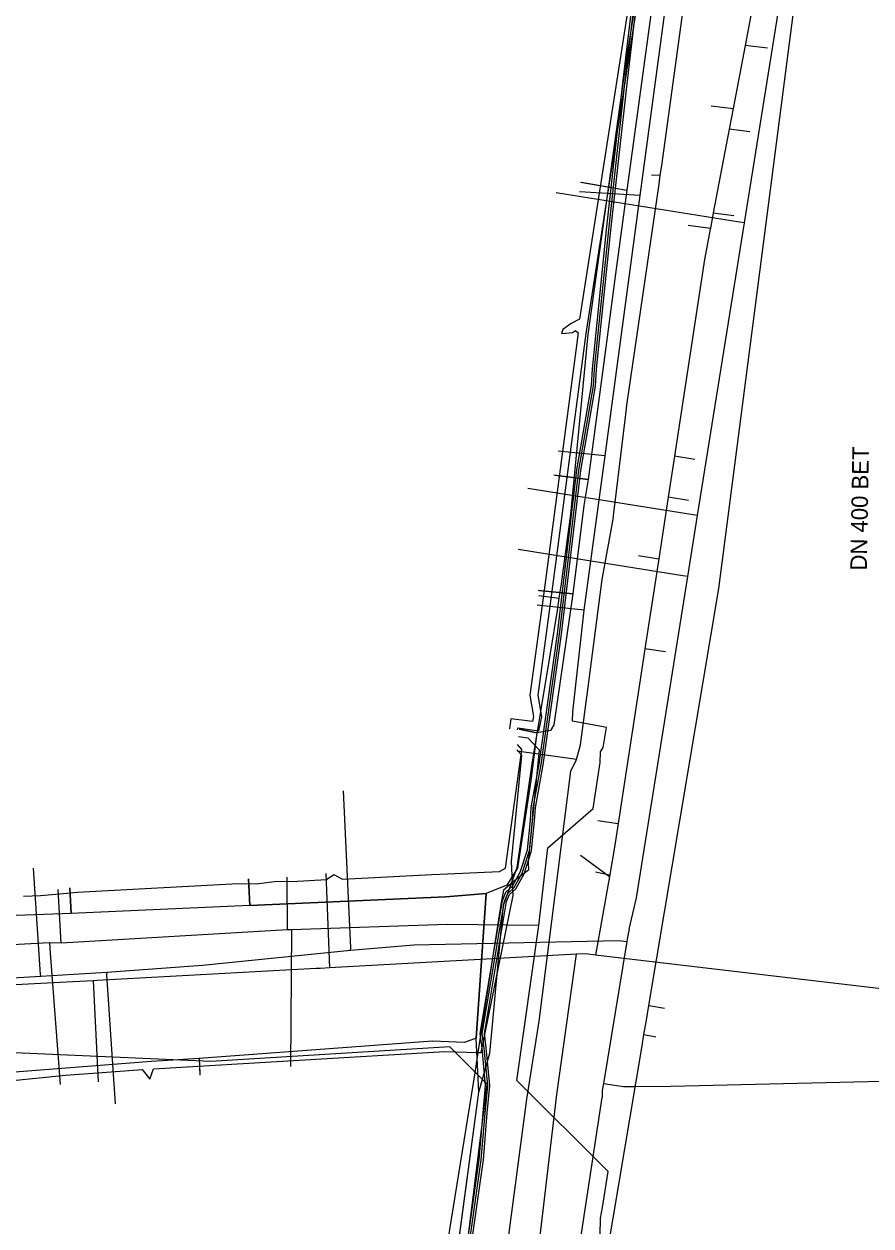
# Model space of a CAD drawing. Extents: x -596228 to -595156, y -1161235 to -1159373.
# Drawn here: x -595422.6 to -595381.6, y -1160891.1 to -1160832.9 of the extents above; entities that cross this region are included whole.
import ezdxf

# ---------------------------------------------------------------- set-up
doc = ezdxf.new("R2010")
doc.units = 0
for name, color, linetype in [('Vrstva 1', 7, 'Continuous'), ('Vrstva 12', 7, 'Continuous'), ('Vrstva 14', 7, 'Continuous'), ('Vrstva 16', 7, 'Continuous'), ('Vrstva 19', 7, 'Continuous'), ('Vrstva 4', 7, 'Continuous'), ('Vrstva 42', 7, 'Continuous'), ('Vrstva 44', 7, 'Continuous'), ('Vrstva 55', 7, 'Continuous'), ('Vrstva 58', 7, 'Continuous'), ('Vrstva 9', 7, 'Continuous')]:
    doc.layers.add(name, color=color, linetype=linetype)

msp = doc.modelspace()

# ---------------------------------------------------------------- linework, layer by layer
at = {"layer": 'Vrstva 1'}
for p, q in [((-595395.692, -1160873.187), (-595394.294, -1160874.206)), ((-595408.036, -1160874.065), (-595407.854, -1160878.639))]:
    msp.add_line(p, q, dxfattribs=at)
at = {"layer": 'Vrstva 12'}
for p, q in [((-595391.27, -1160824.92), (-595393.45, -1160840.98)), ((-595395.69, -1160840.59), (-595393.45, -1160840.98)), ((-595396.93, -1160854.78), (-595395.33, -1160854.98)), ((-595397.69, -1160860.37), (-595396.06, -1160860.53)), ((-595396.73, -1160860.73), (-595396.61, -1160860.04)), ((-595397.72, -1160860.6), (-595396.73, -1160860.73)), ((-595398.66, -1160867.08), (-595397.81, -1160867.26)), ((-595411.77, -1160874.32), (-595411.71, -1160875.61)), ((-595420.43, -1160874.78), (-595420.37, -1160876)), ((-595400.27, -1160875.03), (-595400.75, -1160882.05)), ((-595411.71, -1160875.61), (-595420.37, -1160876)), ((-595400.62, -1160884.65), (-595400.75, -1160882.05)), ((-595414.16, -1160883.02), (-595414.13, -1160883.84)), ((-595401.54, -1160891.52), (-595400.62, -1160884.65))]:
    msp.add_line(p, q, dxfattribs=at)
for points in [[(-595396.61, -1160860.04), (-595396.17, -1160856.67), (-595395.33, -1160847.96), (-595393.5, -1160834.87), (-595391.96, -1160825.25), (-595391.27, -1160820.29), (-595390.52, -1160814.98), (-595390.53, -1160811.25)], [(-595393.45, -1160840.98), (-595394, -1160845.02), (-595394.44, -1160848.34), (-595395.33, -1160854.98)], [(-595395.33, -1160854.98), (-595395.54, -1160856.24), (-595396.06, -1160860.53)], [(-595396.06, -1160860.53), (-595396.98, -1160866.87), (-595397.14, -1160867.14), (-595397.81, -1160867.26)], [(-595400.62, -1160884.65), (-595400.09, -1160882.77), (-595399.97, -1160881.57), (-595399.42, -1160875.6), (-595398.77, -1160873.77), (-595398.04, -1160868.75), (-595397.15, -1160863.4), (-595396.81, -1160861.33), (-595396.73, -1160860.73)], [(-595397.81, -1160867.26), (-595398.1, -1160869.57), (-595398.74, -1160873.81), (-595399.27, -1160874.63), (-595400.27, -1160875.03)], [(-595411.71, -1160875.61), (-595402.22, -1160875.2), (-595400.27, -1160875.03)], [(-595420.37, -1160876), (-595429.24, -1160876.32), (-595436.21, -1160876.71), (-595440.47, -1160876.95)], [(-595400.75, -1160882.05), (-595401.31, -1160882.25), (-595402.87, -1160882.19), (-595414.16, -1160883.02)], [(-595414.16, -1160883.02), (-595416.47, -1160883.18), (-595423.94, -1160883.76), (-595428.13, -1160883.87), (-595432.5, -1160883.79)]]:
    msp.add_lwpolyline(points, dxfattribs=at)
at = {"layer": 'Vrstva 14'}
for p, q in [((-595393.342, -1160876.76), (-595393.4, -1160877.07)), ((-595393.449, -1160877.36), (-595394.58, -1160884.23)), ((-595393.84, -1160877.31), (-595393.45, -1160877.36)), ((-595393.4, -1160877.07), (-595393.449, -1160877.36)), ((-595392.505, -1160881.174), (-595392.386, -1160880.463)), ((-595392.386, -1160880.463), (-595391.63, -1160880.59)), ((-595392.622, -1160881.872), (-595392.505, -1160881.174)), ((-595392.622, -1160881.872), (-595392.04, -1160881.97)), ((-595394.58, -1160884.23), (-595394.64, -1160884.58)), ((-595394.58, -1160884.23), (-595393.62, -1160884.38)), ((-595393.04, -1160884.38), (-595393.042, -1160884.331)), ((-595394.64, -1160884.58), (-595394.65, -1160884.91))]:
    msp.add_line(p, q, dxfattribs=at)
for points in [[(-595392.386, -1160880.463), (-595389, -1160860.26), (-595382.285, -1160808.426), (-595374.317, -1160746.92), (-595371.904, -1160743.843), (-595363.417, -1160733.399), (-595367.988, -1160714.713), (-595370.468, -1160704.744)], [(-595393.342, -1160876.76), (-595392.99, -1160875.24), (-595390.499, -1160859.689), (-595390.026, -1160856.737), (-595387.754, -1160842.558), (-595386.046, -1160831.895), (-595382.445, -1160809.421), (-595378.386, -1160784.054), (-595376.306, -1160771.081), (-595374.576, -1160760.301), (-595372.949, -1160750.146)], [(-595387.754, -1160842.558), (-595387.99, -1160842.52), (-595396.866, -1160841.098)], [(-595390.026, -1160856.737), (-595390.241, -1160856.702), (-595398.246, -1160855.42)], [(-595390.499, -1160859.689), (-595390.742, -1160859.65), (-595398.715, -1160858.373)], [(-595406.84, -1160877.78), (-595406.825, -1160877.67), (-595407.171, -1160870.06)], [(-595421.83, -1160879.04), (-595421.846, -1160878.961), (-595422.188, -1160873.816)], [(-595480.35, -1160881.13), (-595476.74, -1160881.06), (-595458.05, -1160880.32), (-595455.86, -1160880.24), (-595452.25, -1160880.1), (-595447.07, -1160879.89), (-595446.23, -1160879.85), (-595441.06, -1160879.64), (-595438.31, -1160879.54), (-595435.699, -1160879.51), (-595435.21, -1160879.51), (-595434.81, -1160879.5), (-595432.905, -1160879.416), (-595427.729, -1160879.309), (-595426.15, -1160879.29), (-595425.714, -1160879.268), (-595421.83, -1160879.04), (-595418.64, -1160878.84), (-595414.01, -1160878.51), (-595406.84, -1160877.78), (-595403.77, -1160877.53), (-595393.84, -1160877.31)], [(-595418.64, -1160878.84), (-595418.65, -1160878.98), (-595418.239, -1160885.223)], [(-595411.29, -1161007.18), (-595405.35, -1160965.21), (-595403.324, -1160946.542), (-595403.072, -1160944.755), (-595398.92, -1160914.75), (-595397.23, -1160913.67), (-595395.51, -1160899.1), (-595392.712, -1160882.407), (-595392.622, -1160881.872)], [(-595393.62, -1160884.38), (-595393.04, -1160884.38), (-595391.32, -1160884.36), (-595368.12, -1160883.82)], [(-595403.586, -1160941.38), (-595401.229, -1160926.663), (-595399.42, -1160915.372), (-595397.797, -1160905.243), (-595396.846, -1160899.305), (-595396.485, -1160897.021), (-595394.65, -1160884.91)]]:
    msp.add_lwpolyline(points, dxfattribs=at)
at = {"layer": 'Vrstva 16'}
for p, q in [((-595392.25, -1160840.24), (-595391.83, -1160840.25)), ((-595395.89, -1160868.54), (-595398.76, -1160868.14))]:
    msp.add_line(p, q, dxfattribs=at)
msp.add_lwpolyline([(-595399.71, -1160895.73), (-595398.29, -1160884.99), (-595397.7, -1160881.22), (-595396.17, -1160869.12), (-595395.89, -1160868.54), (-595395.69, -1160867.84), (-595395.33, -1160865.05), (-595394.65, -1160859.83), (-595394.12, -1160856.91), (-595394.08, -1160856.58), (-595394.019, -1160856.08), (-595393.47, -1160851.558), (-595393.445, -1160851.385), (-595391.89, -1160840.69), (-595391.83, -1160840.25), (-595391.76, -1160839.78), (-595389.85, -1160825.86)], dxfattribs=at)
at = {"layer": 'Vrstva 19'}
for p, q in [((-595392.81, -1160841.24), (-595395.75, -1160841.05)), ((-595394.5, -1160853.84), (-595396.78, -1160853.62)), ((-595395.51, -1160861.31), (-595397.79, -1160861.08)), ((-595394.6, -1160867.96), (-595394.43, -1160866.99)), ((-595409.88, -1160876.79), (-595409.91, -1160874.24)), ((-595420.85, -1160877.44), (-595421, -1160874.85)), ((-595409.7, -1160876.79), (-595409.74, -1160883.42)), ((-595421.42, -1160877.42), (-595421.382, -1160877.919)), ((-595421.382, -1160877.919), (-595420.9, -1160884.28))]:
    msp.add_line(p, q, dxfattribs=at)
for points in [[(-595396.06, -1160866.24), (-595395.51, -1160861.31), (-595394.5, -1160853.84), (-595392.81, -1160841.24), (-595391.6, -1160832.26), (-595390.88, -1160825.66), (-595389.78, -1160815.51), (-595389.38, -1160803.44), (-595389.404, -1160802.393)], [(-595394.43, -1160866.99), (-595394.6, -1160866.96), (-595396.09, -1160866.69), (-595396.06, -1160866.24)], [(-595394.74, -1160868.69), (-595394.72, -1160868.18), (-595394.6, -1160867.96)], [(-595394.63, -1160890.25), (-595394.36, -1160888.5), (-595398.78, -1160884.09), (-595397.71, -1160876.58), (-595397.28, -1160872.82), (-595395.08, -1160870.92), (-595394.74, -1160868.69)], [(-595397.71, -1160876.58), (-595402.15, -1160876.54), (-595409.7, -1160876.79), (-595409.88, -1160876.79), (-595420.85, -1160877.44), (-595421.42, -1160877.42), (-595424.74, -1160877.6), (-595424.9, -1160877.63), (-595428.23, -1160877.81), (-595433.72, -1160878.02), (-595435.96, -1160878.09), (-595438.16, -1160878.23), (-595442.14, -1160878.46), (-595445.18, -1160878.62), (-595448.84, -1160878.79), (-595449.78, -1160878.83), (-595451.12, -1160878.92), (-595451.38, -1160878.94), (-595453.92, -1160879.07), (-595456.97, -1160879.21), (-595458.04, -1160879.22), (-595474.85, -1160879.93)], [(-595394.75, -1160891.58), (-595394.73, -1160890.76), (-595394.63, -1160890.25)]]:
    msp.add_lwpolyline(points, dxfattribs=at)
at = {"layer": 'Vrstva 42'}
for points in [[(-595398.743, -1160867.114), (-595398.73, -1160867.021), (-595397.716, -1160867.162), (-595397.561, -1160866.474), (-595397.744, -1160865.424), (-595397.111, -1160860.772), (-595395.413, -1160847.915), (-595391.508, -1160822.721), (-595390.89, -1160810.876), (-595390.644, -1160809.221), (-595391.915, -1160801.462), (-595393.78, -1160789.797), (-595393.133, -1160779.844), (-595393.18, -1160779.33), (-595393.154, -1160779.028)], [(-595391.624, -1160810.138), (-595391.538, -1160810.018), (-595391.053, -1160810.05), (-595391.138, -1160810.975), (-595391.917, -1160822.701), (-595392.612, -1160827.51), (-595393.489, -1160827.39), (-595393.667, -1160827.719), (-595393.529, -1160827.949), (-595392.771, -1160828.189), (-595395.741, -1160847.225), (-595396.153, -1160847.432), (-595396.55, -1160847.727), (-595396.62, -1160847.918), (-595396.399, -1160847.899), (-595396.078, -1160847.875), (-595395.93, -1160847.764), (-595395.812, -1160847.881), (-595397.507, -1160860.72), (-595398.148, -1160865.432), (-595397.969, -1160866.464), (-595398.025, -1160866.715), (-595399.071, -1160866.57), (-595399.139, -1160867.058)], [(-595398.69, -1160867.431), (-595398.241, -1160867.493), (-595397.705, -1160868.078), (-595398.228, -1160873.516), (-595398.212, -1160873.91), (-595398.941, -1160874.456), (-595398.988, -1160874.497), (-595399.425, -1160874.879), (-595399.551, -1160875.563), (-595400.664, -1160882.729), (-595400.818, -1160883.719), (-595402.568, -1160894.603)], [(-595422.68, -1160875.17), (-595421.85, -1160875.14), (-595420.91, -1160875.06), (-595420.08, -1160874.98), (-595412.28, -1160874.56), (-595411.4, -1160874.57), (-595410.39, -1160874.44), (-595409.67, -1160874.45), (-595408, -1160874.36), (-595407.648, -1160874.113), (-595407.23, -1160874.34), (-595402.89, -1160874.12), (-595402.14, -1160874.09), (-595399.62, -1160873.97), (-595399.32, -1160873.81), (-595398.574, -1160868.313), (-595398.54, -1160868.06), (-595398.745, -1160867.827)], [(-595416.56, -1160884.02), (-595416.38, -1160883.52), (-595402.268, -1160882.682), (-595400.664, -1160882.729), (-595400.512, -1160882.733), (-595398.962, -1160875.134), (-595398.988, -1160874.497), (-595399.03, -1160873.494), (-595398.535, -1160868.356), (-595398.574, -1160868.313), (-595398.782, -1160868.087)], [(-595445.376, -1160885.066), (-595445.175, -1160884.567), (-595440.05, -1160884.574), (-595435.455, -1160884.313), (-595432.92, -1160884.304), (-595432.96, -1160885.17), (-595433.189, -1160885.558), (-595432.645, -1160884.987), (-595432.658, -1160884.278), (-595427, -1160884.159), (-595423.517, -1160884.12), (-595420.64, -1160883.839), (-595418.43, -1160883.67)], [(-595418.43, -1160883.67), (-595416.93, -1160883.56), (-595416.56, -1160884.02)]]:
    msp.add_lwpolyline(points, dxfattribs=at)
at = {"layer": 'Vrstva 44'}
for points in [[(-595401.459, -1160894.008), (-595400.599, -1160887.919), (-595400.41, -1160885.661), (-595400.29, -1160884.34), (-595400.459, -1160882.531), (-595400.551, -1160881.818), (-595399.467, -1160875.373), (-595399.304, -1160874.972), (-595398.99, -1160874.677), (-595398.612, -1160874.01), (-595398.259, -1160872.929), (-595398.12, -1160871.502), (-595398.079, -1160870.868), (-595397.699, -1160868.774), (-595396.809, -1160862.457), (-595395.879, -1160854.515), (-595395.16, -1160850.439), (-595395.12, -1160849.623), (-595394.429, -1160842.889), (-595393.639, -1160835.799), (-595392.709, -1160827.918)], [(-595401.261, -1160894.032), (-595400.401, -1160887.941), (-595400.21, -1160885.679), (-595400.09, -1160884.34), (-595400.261, -1160882.509), (-595400.349, -1160881.822), (-595399.273, -1160875.427), (-595399.136, -1160875.088), (-595398.83, -1160874.803), (-595398.428, -1160874.09), (-595398.062, -1160872.971), (-595397.92, -1160871.518), (-595397.881, -1160870.892), (-595397.501, -1160868.806), (-595396.611, -1160862.483), (-595395.681, -1160854.545), (-595394.961, -1160850.461), (-595394.92, -1160849.637), (-595394.23, -1160842.911), (-595393.441, -1160835.821), (-595392.511, -1160827.942)]]:
    msp.add_lwpolyline(points, dxfattribs=at)
at = {"layer": 'Vrstva 55'}
msp.add_lwpolyline([(-595411.46, -1160939.37), (-595406.666, -1160938.79), (-595406.76, -1160937.08), (-595400.21, -1160884.27), (-595402.02, -1160882.46), (-595413.593, -1160883.169), (-595423.46, -1160882.73)], dxfattribs=at)
at = {"layer": 'Vrstva 58'}
for p, q in [((-595391.27, -1160824.92), (-595393.45, -1160840.98)), ((-595395.65, -1160840.59), (-595393.45, -1160840.98)), ((-595395.33, -1160854.98), (-595396.98, -1160854.77)), ((-595396.06, -1160860.53), (-595397.74, -1160860.37)), ((-595397.81, -1160867.26), (-595398.66, -1160867.08)), ((-595411.71, -1160875.61), (-595411.77, -1160874.32)), ((-595420.37, -1160876), (-595420.43, -1160874.76)), ((-595400.27, -1160875.03), (-595400.75, -1160882.05)), ((-595411.71, -1160875.61), (-595420.37, -1160876)), ((-595414.16, -1160883.02), (-595414.14, -1160883.76))]:
    msp.add_line(p, q, dxfattribs=at)
for points in [[(-595395.06, -1160850.45), (-595395.02, -1160849.63), (-595394.33, -1160842.9), (-595393.54, -1160835.81), (-595392.61, -1160827.93), (-595392.3, -1160825.51), (-595391.91, -1160822.03), (-595391.75, -1160818.59), (-595391.39, -1160815.54), (-595391.1, -1160813.32), (-595390.62, -1160810.83), (-595390.6, -1160810.05), (-595390.85, -1160808.64), (-595391, -1160804.88), (-595391.32, -1160800.61), (-595391.89, -1160798.02), (-595392.53, -1160792.59), (-595393.55, -1160787.42), (-595394.28, -1160780.83), (-595394.55, -1160777.96), (-595394.87, -1160777.33), (-595395.57, -1160777.18), (-595399.97, -1160777.48), (-595400.45, -1160777.35)], [(-595393.45, -1160840.98), (-595394, -1160845.02), (-595394.44, -1160848.34), (-595395.33, -1160854.98)], [(-595397.98, -1160870.88), (-595397.6, -1160868.79), (-595396.71, -1160862.47), (-595395.78, -1160854.53), (-595395.06, -1160850.45)], [(-595395.33, -1160854.98), (-595395.54, -1160856.24), (-595396.06, -1160860.53)], [(-595396.06, -1160860.53), (-595396.98, -1160866.87), (-595397.14, -1160867.14), (-595397.81, -1160867.26)], [(-595397.81, -1160867.26), (-595398.1, -1160869.57), (-595398.74, -1160873.81), (-595399.27, -1160874.63), (-595400.27, -1160875.03)], [(-595401.36, -1160894.02), (-595400.5, -1160887.93), (-595400.31, -1160885.67), (-595400.19, -1160884.34), (-595400.36, -1160882.52), (-595400.45, -1160881.82), (-595399.37, -1160875.4), (-595399.22, -1160875.03), (-595398.91, -1160874.74), (-595398.52, -1160874.05), (-595398.16, -1160872.95), (-595398.02, -1160871.51), (-595397.98, -1160870.88)], [(-595411.5, -1160983.2), (-595411.14, -1160979.42), (-595408.91, -1160960.35), (-595410.42, -1160955.78), (-595411.56, -1160953.9), (-595411.21, -1160951.78), (-595410.16, -1160941.32), (-595408.64, -1160938.53), (-595407.98, -1160933.92), (-595405.58, -1160918.39), (-595404.98, -1160914.76), (-595403.22, -1160903.59), (-595402.29, -1160897.41), (-595401.59, -1160891.85), (-595400.62, -1160884.65), (-595400.75, -1160882.05), (-595400.27, -1160875.03), (-595402.22, -1160875.2), (-595411.71, -1160875.61), (-595420.37, -1160876), (-595429.24, -1160876.32), (-595436.21, -1160876.71), (-595440.47, -1160876.95)], [(-595411.71, -1160875.61), (-595402.22, -1160875.2), (-595400.27, -1160875.03)], [(-595420.37, -1160876), (-595429.24, -1160876.32), (-595436.21, -1160876.71)], [(-595400.75, -1160882.05), (-595401.31, -1160882.25), (-595402.87, -1160882.19), (-595414.16, -1160883.02)], [(-595401.54, -1160891.52), (-595400.62, -1160884.65), (-595400.75, -1160882.05)], [(-595414.16, -1160883.02), (-595416.47, -1160883.18), (-595423.94, -1160883.76), (-595428.13, -1160883.87), (-595432.5, -1160883.79)]]:
    msp.add_lwpolyline(points, dxfattribs=at)
at = {"layer": 'Vrstva 9'}
for p, q in [((-595386.633, -1160834.106), (-595387.723, -1160833.966)), ((-595389.371, -1160836.89), (-595388.305, -1160837.027)), ((-595387.5, -1160838.148), (-595388.492, -1160838.021)), ((-595388.271, -1160842.213), (-595389.263, -1160842.086)), ((-595390.485, -1160842.675), (-595389.401, -1160842.814)), ((-595390.158, -1160854.015), (-595391.146, -1160853.864)), ((-595390.462, -1160856.002), (-595391.45, -1160855.851)), ((-595392.893, -1160858.674), (-595391.905, -1160858.825)), ((-595391.583, -1160863.336), (-595392.572, -1160863.185)), ((-595394.855, -1160871.502), (-595393.866, -1160871.653)), ((-595394.965, -1160873.991), (-595394.279, -1160874.128)), ((-595396.843, -1160884.771), (-595395.885, -1160877.981)), ((-595380.588, -1160879.723), (-595394.967, -1160878.021)), ((-595419.042, -1160884.151), (-595419.291, -1160879.261)), ((-595400.58, -1160916.76), (-595396.843, -1160884.771))]:
    msp.add_line(p, q, dxfattribs=at)
for points in [[(-595383.099, -1160809.629), (-595383.516, -1160811.822), (-595384.841, -1160818.789), (-595385.319, -1160821.299), (-595385.817, -1160823.927), (-595386.362, -1160826.791), (-595387.154, -1160830.954), (-595387.723, -1160833.966), (-595388.305, -1160837.027), (-595388.492, -1160838.021), (-595389.261, -1160842.076), (-595389.263, -1160842.086), (-595389.401, -1160842.814), (-595389.41, -1160842.864), (-595389.69, -1160844.34)], [(-595389.69, -1160844.34), (-595391.146, -1160853.864), (-595391.45, -1160855.851), (-595391.905, -1160858.825), (-595392.572, -1160863.185), (-595392.689, -1160863.951), (-595393.866, -1160871.653), (-595394.025, -1160872.69)], [(-595394.025, -1160872.69), (-595394.293, -1160874.206), (-595394.967, -1160878.017)], [(-595395.885, -1160877.981), (-595407.854, -1160878.639), (-595408.288, -1160878.663), (-595408.496, -1160878.674), (-595419.105, -1160879.251), (-595419.291, -1160879.261), (-595420.289, -1160879.315), (-595423.699, -1160879.5)], [(-595394.967, -1160878.021), (-595395.438, -1160877.965), (-595395.885, -1160877.981)]]:
    msp.add_lwpolyline(points, dxfattribs=at)

# ---------------------------------------------------------------- texts
at = {"layer": 'Vrstva 4'}
msp.add_text('DN 400 BET', height=0.8, rotation=89, dxfattribs=at).set_placement((-595381.828, -1160859.402))

doc.saveas('drawing.dxf')
